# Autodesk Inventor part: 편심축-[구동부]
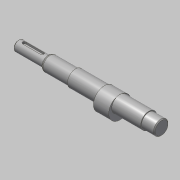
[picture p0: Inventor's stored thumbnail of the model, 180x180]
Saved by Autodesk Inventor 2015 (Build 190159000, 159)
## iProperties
Created: 2017-08
Part Number: 편심축-[구동부]
Material: 강철, 연강
Document SubType Name: Modeling
Designer: mduedu
Density: 1 g/cm^3
Appearance: 강철
Author: mduedu
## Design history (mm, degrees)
sketch "스케치1"
  geometry: L1 (0, 0)-(168, 0); L2 (168, 0)-(168, 8.5); L3 (168, 8.5)-(153, 8.5); L4 (153, 8.5)-(153, 9.5); L5 (153, 9.5)-(67, 9.5); L6 (67, 9.5)-(67, 8.5); L7 (67, 8.5)-(35, 8.5); L8 (35, 8.5)-(35, 6); L9 (35, 6)-(0, 6); L10 (0, 6)-(0, 0)
  constraints: 20 end point, 6 parallel, 2 collinear, 2 perpendicular, 1 horizontal
  dimensions: "d0" = 168 distance of L1.start L1.end; "d1" = 17 diameter of L3 L1; "d2" = 19 diameter of L5 L1; "d3" = 12 diameter of L9 L1; "d4" = 35 distance of L8.end L9.end; "d5" = 15 distance of L2.end L3.end; "d6" = 86 distance of L4.end L5.end
revolve "회전1" sketch "스케치1" stored, may be unused: angle "d7" = 90 deg
node "작업 평면1"
sketch "스케치2"
  geometry: C1 r 9.5 at (0, 0) reference; C2 r 13 at (0, -3.5); 1 further point
  constraints: 1 centre point, 1 tangent, 1 vertical alignment
  dimensions: "d8" = 3.5 distance of point (0, 0) C2.centre
extrude "돌출1" join sketch "스케치2" stored distance "d9" = 18; taper "d10" = 0 deg
chamfer "모따기1" distance "d11" = 1; stored, may be unused: second distance "d12" = 2, angle "d13" = 45 deg
node "작업 평면2"
sketch "스케치3"
  geometry: L1 (10.5, -2)-(-10.5, -2); L2 (-10.5, -2)-(-10.5, 2); L3 (-10.5, 2)-(10.5, 2); L4 (10.5, 2)-(10.5, -2); L5 (17.5, 6)-(17.5, -6) reference; L6 (-17.5, 8.5)-(-17.5, -8.5) reference; A1 r 2 centre (10.5, 0) between (10.5, -2) and (10.5, 2); A2 r 2 centre (-10.5, 0) between (-10.5, 2) and (-10.5, -2); A3 r 2 centre (10.5, 0) between (10.5, 2) and (10.5, -2); A4 r 2 centre (-10.5, 0) between (-10.5, -2) and (-10.5, 2); 1 further point
  constraints: 8 end point, 8 point on circle, 4 centre point, 2 midpoint, 2 parallel, 1 horizontal, 1 horizontal alignment, 1 perpendicular
  dimensions: "d14" = 25 dimension on A2 A1; "d16" = 4 distance between parallel lines of L3 L1; "d17" = 5 distance edge to line of A1 L5; "d46" = 5 distance edge to line of A2 L6 (derived)
extrude "돌출2" cut sketch "스케치3" distance "d18" = 2.5; taper "d19" = 0 deg
chamfer "모따기2" distance "d20" = 1; stored, may be unused: second distance "d21" = 2, angle "d22" = 45 deg
chamfer "모따기4" distance "d39" = 1.82; stored, may be unused: second distance "d40" = 2, angle "d41" = 30 deg
fillet "모깎기4" dims "d45" = 2
hole "구멍1" diameter "d29" = 3.242; stored, may be unused: countersink angle "d33" = 90 deg, drill point angle "d35" = 118 deg; dims "d30" = 8, "d31" = 4, "d32" = 2, "d34" = 10, "d36" = 10, "d37" = 10
node "솔리드1"
node "절단 모서리 투영1"
